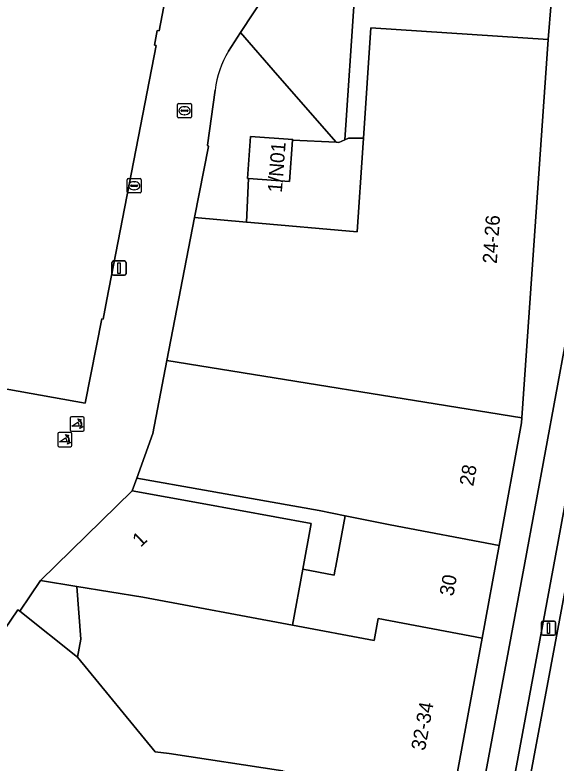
# Model space of a CAD drawing. Extents: x 161402 to 161933, y 381647 to 382315.
# Drawn here: x 161869.9 to 161907.9, y 382023.3 to 382075.9 of the extents above; entities that cross this region are included whole.
import ezdxf

# ---------------------------------------------------------------- set-up
doc = ezdxf.new("R2010")
doc.units = 0
for name, color, linetype in [('IMGEO_Erf', 7, 'Continuous'), ('IMGEO_Fietspad_gesloten', 7, 'Continuous'), ('IMGEO_Kolk', 7, 'Continuous'), ('IMGEO_Lichtmast', 7, 'Continuous'), ('IMGEO_Pand', 7, 'Continuous'), ('IMGEO_Pand_nummerreeks', 7, 'Continuous'), ('IMGEO_Parkeervlak_open', 7, 'Continuous'), ('IMGEO_Poller', 7, 'Continuous'), ('IMGEO_Rijbaan_lokaal_open', 7, 'Continuous'), ('IMGEO_Rioolput', 7, 'Continuous'), ('IMGEO_Verkeerseiland_open', 7, 'Continuous'), ('IMGEO_Voetpad_open', 7, 'Continuous')]:
    doc.layers.add(name, color=color, linetype=linetype)

msp = doc.modelspace()

# ---------------------------------------------------------------- linework, layer by layer
at = {"layer": 'IMGEO_Erf'}
for points in [[(161883.185, 382042.477), (161878.423, 382043.323), (161878.093, 382042.427), (161883.013, 382041.531), (161890.672, 382040.135), (161890.09, 382036.919), (161892.299, 382036.504), (161892.353, 382036.794), (161892.415, 382037.126), (161893.077, 382040.671), (161891.251, 382041.042)], [(161874.211, 382035.706), (161871.647, 382036.119), (161870.203, 382033.963), (161874.247, 382030.726), (161874.485, 382031.994)]]:
    msp.add_lwpolyline(points, close=True, dxfattribs=at)
at = {"layer": 'IMGEO_Fietspad_gesloten'}
for points in [[(161910.061, 382061.001), (161905.702, 382037.375), (161898.752, 382000), (161887.89, 381941.593), (161886.669, 381935.154), (161880.56, 381902.497), (161879.486, 381896.758), (161857.65, 381780.798), (161851.928, 381750), (161842.232, 381697.819)], [(161881.54, 381896.271), (161882.623, 381902.093), (161888.398, 381933.147), (161890.059, 381942.083), (161900.83, 382000), (161908.061, 382038.88), (161912.039, 382060.567)]]:
    msp.add_lwpolyline(points, dxfattribs=at)
at = {"layer": 'IMGEO_Kolk'}
for p, q in [((161877.739, 382063.468), (161877.739, 382064.32)), ((161877.814, 382064.394), (161878.666, 382064.394)), ((161878.227, 382064.174), (161878.252, 382064.174)), ((161878.74, 382064.32), (161878.74, 382063.468)), ((161877.998, 382063.888), (161877.998, 382063.9)), ((161878.436, 382063.851), (161878.038, 382063.851)), ((161878.041, 382063.937), (161878.439, 382063.937)), ((161878.25, 382063.614), (161878.225, 382063.614)), ((161878.482, 382063.9), (161878.482, 382063.888)), ((161878.666, 382063.394), (161877.814, 382063.394))]:
    msp.add_line(p, q, dxfattribs=at)
for points in [[(161877.739, 382063.468), (161877.739, 382064.32)], [(161877.814, 382064.394), (161878.666, 382064.394)], [(161878.74, 382064.32), (161878.74, 382063.468)], [(161878.666, 382063.394), (161877.814, 382063.394)]]:
    msp.add_lwpolyline(points, dxfattribs=at)
for centre, radius, start, end in [((161877.816, 382064.318), 0.0765, 91.552, 178.448), ((161877.816, 382064.318), 0.0765, 91.552, 178.448), ((161878.664, 382064.318), 0.0765, 1.552, 88.448), ((161878.664, 382064.318), 0.0765, 1.552, 88.448), ((161878.038, 382063.897), 0.0403, 85.8775, 175.7526), ((161878.035, 382063.887), 0.0366, 178.938, 274.7102), ((161878.439, 382063.894), 0.043, 264.8664, 352.4533), ((161878.443, 382063.899), 0.0386, 1.7309, 96.639), ((161877.816, 382063.47), 0.0765, 181.552, 268.448), ((161877.816, 382063.47), 0.0765, 181.552, 268.448), ((161878.664, 382063.47), 0.0765, 271.552, 358.448), ((161878.664, 382063.47), 0.0765, 271.552, 358.448)]:
    msp.add_arc(centre, radius, start, end, dxfattribs=at)
for centre, major_axis, ratio, start_param, end_param in [((161878.226, 382063.894), (-0.387, 0.002), 0.722429, 4.712389, 7.853982), ((161878.251, 382063.894), (-0.39, 0.002), 0.717154, 1.570796, 4.712389)]:
    msp.add_ellipse(centre, major_axis=major_axis, ratio=ratio, start_param=start_param, end_param=end_param, dxfattribs=at)
at = {"layer": 'IMGEO_Lichtmast'}
for p, q in [((161876.675, 382057.704), (161876.675, 382058.504)), ((161876.675, 382058.504), (161876.675, 382057.704)), ((161876.775, 382058.604), (161877.565, 382058.604)), ((161877.565, 382058.604), (161876.775, 382058.604)), ((161877.665, 382058.504), (161877.665, 382057.704)), ((161877.665, 382057.704), (161877.665, 382058.504)), ((161877.565, 382057.604), (161876.775, 382057.604)), ((161876.775, 382057.604), (161877.565, 382057.604)), ((161906.872, 382032.376), (161906.872, 382033.176)), ((161906.872, 382033.176), (161906.872, 382032.376)), ((161906.972, 382033.276), (161907.762, 382033.276)), ((161907.762, 382033.276), (161906.972, 382033.276)), ((161907.862, 382033.176), (161907.862, 382032.376)), ((161907.862, 382032.376), (161907.862, 382033.176)), ((161907.762, 382032.276), (161906.972, 382032.276)), ((161906.972, 382032.276), (161907.762, 382032.276))]:
    msp.add_line(p, q, dxfattribs=at)
for points in [[(161877.095, 382058.479), (161877.245, 382058.479), (161877.245, 382057.729), (161877.095, 382057.729), (161877.095, 382058.479)], [(161907.292, 382033.151), (161907.442, 382033.151), (161907.442, 382032.401), (161907.292, 382032.401), (161907.292, 382033.151)]]:
    msp.add_lwpolyline(points, dxfattribs=at)
for centre, start, end in [((161876.775, 382058.504), 90, 180), ((161876.775, 382058.504), 90, 180), ((161877.565, 382058.504), 0, 90), ((161877.565, 382058.504), 360, 90), ((161876.775, 382057.704), 180, 270), ((161876.775, 382057.704), 180, 270), ((161877.565, 382057.704), 270, 0), ((161877.565, 382057.704), 270, 0), ((161906.972, 382033.176), 90, 180), ((161906.972, 382033.176), 90, 180), ((161907.762, 382033.176), 0, 90), ((161907.762, 382033.176), 360, 90), ((161906.972, 382032.376), 180, 270), ((161906.972, 382032.376), 180, 270), ((161907.762, 382032.376), 270, 0), ((161907.762, 382032.376), 270, 0)]:
    msp.add_arc(centre, 0.1, start, end, dxfattribs=at)
at = {"layer": 'IMGEO_Pand'}
for points in [[(161881.604, 382083.709), (161864.747, 382086.071), (161864.705, 382087.108), (161857.022, 382088.5), (161857.282, 382089.936), (161856.514, 382090.075), (161856.605, 382090.577), (161849.637, 382091.837), (161848.409, 382092.059), (161845.824, 382077.508), (161842.463, 382058.722), (161841.73, 382054.571), (161852.314, 382052.645), (161867.831, 382049.852), (161874.803, 382048.597), (161875.966, 382054.535), (161876.056, 382054.517), (161876.327, 382055.897), (161879.777, 382073.754), (161879.674, 382073.772), (161879.866, 382074.825), (161879.984, 382074.802), (161880.941, 382079.709), (161880.846, 382079.728)], [(161907.356, 382074.185), (161894.871, 382075.011), (161894.356, 382067.242), (161894.311, 382066.556), (161893.92, 382060.648), (161886.444, 382061.304), (161886.126, 382061.332), (161882.474, 382061.653), (161880.537, 382051.6), (161905.504, 382047.572)], [(161889.381, 382067.098), (161889.384, 382067.141), (161886.417, 382067.362), (161886.197, 382064.406), (161886.272, 382064.4), (161889.164, 382064.185)], [(161905.48, 382047.22), (161905.504, 382047.572), (161880.537, 382051.6), (161879.548, 382046.468), (161878.423, 382043.323), (161883.185, 382042.477), (161891.251, 382041.042), (161893.077, 382040.671), (161896.236, 382040.03), (161903.899, 382038.59)], [(161890.672, 382040.135), (161883.013, 382041.531), (161878.093, 382042.427), (161871.647, 382036.119), (161874.211, 382035.706), (161878.84, 382034.96), (161889.378, 382032.986), (161890.09, 382036.919)], [(161903.899, 382038.59), (161896.236, 382040.03), (161893.077, 382040.671), (161892.415, 382037.126), (161892.353, 382036.794), (161892.299, 382036.504), (161890.09, 382036.919), (161889.378, 382032.986), (161895.112, 382031.912), (161895.4, 382033.445), (161902.704, 382032.073)], [(161902.704, 382032.073), (161895.4, 382033.445), (161895.112, 382031.912), (161889.378, 382032.986), (161878.84, 382034.96), (161874.211, 382035.706), (161874.485, 382031.994), (161874.247, 382030.726), (161879.703, 382024.079), (161880.709, 382023.945), (161888.702, 382022.741), (161900.585, 382020.509)]]:
    msp.add_lwpolyline(points, close=True, dxfattribs=at)
msp.add_lwpolyline([(161888.702, 382022.741), (161880.709, 382023.945), (161879.703, 382024.079), (161874.247, 382030.726), (161870.203, 382033.963), (161870.07, 382034.054), (161863.165, 382023.932), (161863.131, 382023.567), (161869.815, 382022.328)], dxfattribs=at)
at = {"layer": 'IMGEO_Parkeervlak_open'}
msp.add_lwpolyline([(161909.017, 382036.526), (161908.748, 382036.59), (161905.714, 382020.292), (161906.013, 382020.197)], dxfattribs=at)
at = {"layer": 'IMGEO_Poller'}
for p, q in [((161873.732, 382047.537), (161873.732, 382046.73)), ((161873.732, 382047.537), (161873.732, 382046.73)), ((161874.634, 382047.632), (161873.826, 382047.632)), ((161874.634, 382047.632), (161873.826, 382047.632)), ((161874.728, 382046.73), (161874.728, 382047.537)), ((161874.728, 382046.73), (161874.728, 382047.537)), ((161872.86, 382046.44), (161872.86, 382045.633)), ((161872.86, 382046.44), (161872.86, 382045.633)), ((161873.762, 382046.535), (161872.954, 382046.535)), ((161873.762, 382046.535), (161872.954, 382046.535)), ((161873.826, 382046.635), (161874.634, 382046.635)), ((161873.826, 382046.635), (161874.634, 382046.635)), ((161873.856, 382045.633), (161873.856, 382046.44)), ((161873.856, 382045.633), (161873.856, 382046.44)), ((161872.954, 382045.538), (161873.762, 382045.538)), ((161872.954, 382045.538), (161873.762, 382045.538))]:
    msp.add_line(p, q, dxfattribs=at)
for points in [[(161874.367, 382046.988), (161873.854, 382046.988), (161874.284, 382047.263)], [(161874.411, 382047.361), (161874.399, 382047.288), (161874.274, 382047.493)], [(161874.274, 382047.493), (161874.505, 382047.427), (161874.434, 382047.395)], [(161874.427, 382046.816), (161874.493, 382047.047), (161874.523, 382046.979)], [(161874.559, 382046.952), (161874.631, 382046.941), (161874.427, 382046.816)], [(161873.539, 382046.264), (161873.527, 382046.191), (161873.402, 382046.396)], [(161873.402, 382046.396), (161873.633, 382046.33), (161873.562, 382046.298)], [(161873.495, 382045.891), (161872.982, 382045.891), (161873.412, 382046.166)], [(161873.555, 382045.719), (161873.621, 382045.95), (161873.651, 382045.882)], [(161873.687, 382045.855), (161873.759, 382045.844), (161873.555, 382045.719)]]:
    msp.add_lwpolyline(points, dxfattribs=at)
for centre, radius, start, end in [((161873.826, 382047.537), 0.0946, 90, 180), ((161873.826, 382047.537), 0.0946, 90, 180), ((161874.039, 382047.038), 0.332, 351.3247, 42.4854), ((161874.053, 382047.048), 0.476, 351.7527, 41.1691), ((161874.053, 382047.048), 0.516, 349.3569, 42.2912), ((161874.634, 382047.537), 0.0946, 0, 90), ((161874.634, 382047.537), 0.0946, 0, 90), ((161873.826, 382046.73), 0.0946, 180, 270), ((161873.826, 382046.73), 0.0946, 180, 270), ((161874.634, 382046.73), 0.0946, 270, 0), ((161874.634, 382046.73), 0.0946, 270, 0), ((161872.954, 382046.44), 0.0946, 90, 180), ((161872.954, 382046.44), 0.0946, 90, 180), ((161873.181, 382045.951), 0.476, 351.7527, 41.1691), ((161873.181, 382045.951), 0.516, 349.3569, 42.2912), ((161873.762, 382046.44), 0.0946, 0, 90), ((161873.762, 382046.44), 0.0946, 0, 90), ((161873.167, 382045.941), 0.332, 351.3247, 42.4854), ((161872.954, 382045.633), 0.0946, 180, 270), ((161872.954, 382045.633), 0.0946, 180, 270), ((161873.762, 382045.633), 0.0946, 270, 0), ((161873.762, 382045.633), 0.0946, 270, 0)]:
    msp.add_arc(centre, radius, start, end, dxfattribs=at)
at = {"layer": 'IMGEO_Rijbaan_lokaal_open'}
for points in [[(161880.941, 382079.709), (161879.984, 382074.802), (161879.866, 382074.825), (161879.674, 382073.772), (161879.777, 382073.754), (161876.327, 382055.897), (161876.056, 382054.517), (161875.966, 382054.535), (161874.803, 382048.597), (161867.831, 382049.852), (161863.275, 382024.22), (161862.931, 382023.789), (161863.131, 382023.567), (161863.165, 382023.932), (161870.07, 382034.054), (161870.203, 382033.963), (161871.647, 382036.119), (161878.093, 382042.427), (161878.423, 382043.323), (161879.548, 382046.468), (161880.537, 382051.6), (161882.474, 382061.653)], [(161884.863, 382073.351), (161885.72, 382074.668), (161887.537, 382077.461)], [(161882.474, 382061.653), (161883.474, 382066.647), (161883.395, 382066.737), (161883.925, 382070.629)]]:
    msp.add_lwpolyline(points, dxfattribs=at)
msp.add_arc((161891.134, 382069.667), 7.273, 149.5698, 172.4024, dxfattribs=at)
at = {"layer": 'IMGEO_Rioolput'}
for p, q in [((161881.278, 382068.747), (161881.278, 382069.599)), ((161881.353, 382069.673), (161882.205, 382069.673)), ((161881.766, 382069.453), (161881.791, 382069.453)), ((161882.279, 382069.599), (161882.279, 382068.747)), ((161881.537, 382069.167), (161881.537, 382069.179)), ((161881.975, 382069.13), (161881.577, 382069.13)), ((161881.58, 382069.216), (161881.978, 382069.216)), ((161881.789, 382068.893), (161881.764, 382068.893)), ((161882.021, 382069.179), (161882.021, 382069.167)), ((161882.205, 382068.673), (161881.353, 382068.673))]:
    msp.add_line(p, q, dxfattribs=at)
for points in [[(161881.278, 382068.747), (161881.278, 382069.599)], [(161881.353, 382069.673), (161882.205, 382069.673)], [(161882.279, 382069.599), (161882.279, 382068.747)], [(161882.205, 382068.673), (161881.353, 382068.673)]]:
    msp.add_lwpolyline(points, dxfattribs=at)
for centre, radius, start, end in [((161881.355, 382069.597), 0.0765, 91.552, 178.448), ((161881.355, 382069.597), 0.0765, 91.552, 178.448), ((161882.203, 382069.597), 0.0765, 1.552, 88.448), ((161882.203, 382069.597), 0.0765, 1.552, 88.448), ((161881.577, 382069.176), 0.0403, 85.8775, 175.7526), ((161881.574, 382069.166), 0.0366, 178.938, 274.7102), ((161881.978, 382069.173), 0.043, 264.8664, 352.4533), ((161881.982, 382069.178), 0.0386, 1.7309, 96.639), ((161881.355, 382068.749), 0.0765, 181.552, 268.448), ((161881.355, 382068.749), 0.0765, 181.552, 268.448), ((161882.203, 382068.749), 0.0765, 271.552, 358.448), ((161882.203, 382068.749), 0.0765, 271.552, 358.448)]:
    msp.add_arc(centre, radius, start, end, dxfattribs=at)
for centre, major_axis, ratio, start_param, end_param in [((161881.765, 382069.173), (-0.387, 0.002), 0.722429, 4.712389, 7.853982), ((161881.79, 382069.173), (-0.39, 0.002), 0.717154, 1.570796, 4.712389)]:
    msp.add_ellipse(centre, major_axis=major_axis, ratio=ratio, start_param=start_param, end_param=end_param, dxfattribs=at)
at = {"layer": 'IMGEO_Verkeerseiland_open'}
for points in [[(161912.039, 382060.567), (161908.061, 382038.88), (161900.83, 382000), (161890.059, 381942.083), (161888.398, 381933.147), (161882.623, 381902.093), (161881.54, 381896.271), (161869.899, 381834.602), (161872.587, 381834.08), (161872.769, 381835.211)], [(161906.013, 382020.197), (161905.714, 382020.292), (161908.748, 382036.59), (161909.017, 382036.526)]]:
    msp.add_lwpolyline(points, dxfattribs=at)
at = {"layer": 'IMGEO_Voetpad_open'}
for points in [[(161887.537, 382077.461), (161885.72, 382074.668), (161888.323, 382071.67), (161892.436, 382066.953), (161892.619, 382066.944), (161893.044, 382067.129), (161893.731, 382077.231), (161895.501, 382077.17)], [(161907.56, 382076.762), (161907.356, 382074.185), (161905.504, 382047.572), (161905.48, 382047.22), (161903.899, 382038.59), (161902.704, 382032.073), (161900.585, 382020.509), (161898.721, 382010.338), (161897.556, 382003.977), (161896.827, 382000), (161896.379, 381997.555), (161895.455, 381992.511), (161894.351, 381986.526), (161893.665, 381984.233), (161892.707, 381978.796), (161891.821, 381973.764), (161889.826, 381962.441), (161889.787, 381962.219), (161888.825, 381956.914), (161887.991, 381952.322), (161887.211, 381948.02), (161886.859, 381948.049)], [(161886.417, 382067.362), (161889.384, 382067.141), (161889.381, 382067.098), (161892.436, 382066.953), (161888.323, 382071.67), (161885.72, 382074.668), (161884.863, 382073.351)], [(161883.925, 382070.629), (161883.395, 382066.737), (161883.474, 382066.647), (161882.474, 382061.653), (161886.126, 382061.332), (161886.272, 382064.4), (161886.197, 382064.406), (161886.417, 382067.362)], [(161887.89, 381941.593), (161898.752, 382000), (161905.702, 382037.375), (161910.061, 382061.001)]]:
    msp.add_lwpolyline(points, dxfattribs=at)
for points in [[(161907.56, 382076.762), (161895.499, 382077.1), (161895.501, 382077.17), (161893.731, 382077.231), (161893.044, 382067.129), (161893.307, 382067.242), (161894.356, 382067.242), (161894.871, 382075.011), (161907.356, 382074.185)], [(161894.311, 382066.556), (161894.356, 382067.242), (161893.307, 382067.242), (161893.044, 382067.129), (161892.619, 382066.944), (161892.436, 382066.953), (161889.381, 382067.098), (161889.164, 382064.185), (161886.272, 382064.4), (161886.126, 382061.332), (161886.444, 382061.304), (161893.92, 382060.648)]]:
    msp.add_lwpolyline(points, close=True, dxfattribs=at)
msp.add_arc((161891.134, 382069.667), 7.273, 149.5698, 172.4024, dxfattribs=at)

# ---------------------------------------------------------------- texts
at = {"layer": 'IMGEO_Pand_nummerreeks'}
for s, rotation, p in [('1/N01', 85.5483, (161888.62, 382063.384)), ('24-26', 86.0182, (161903.731, 382058.384)), ('28', 79.8646, (161902.077, 382042.715)), ('1', 44.2896, (161878.695, 382038.421)), ('30', 79.6182, (161900.675, 382034.975)), ('32-34', 79.6182, (161898.683, 382024.113))]:
    msp.add_text(s, height=1, rotation=rotation, dxfattribs=at).set_placement(p)

doc.saveas('drawing.dxf')
